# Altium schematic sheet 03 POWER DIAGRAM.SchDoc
size 420 x 297 mm
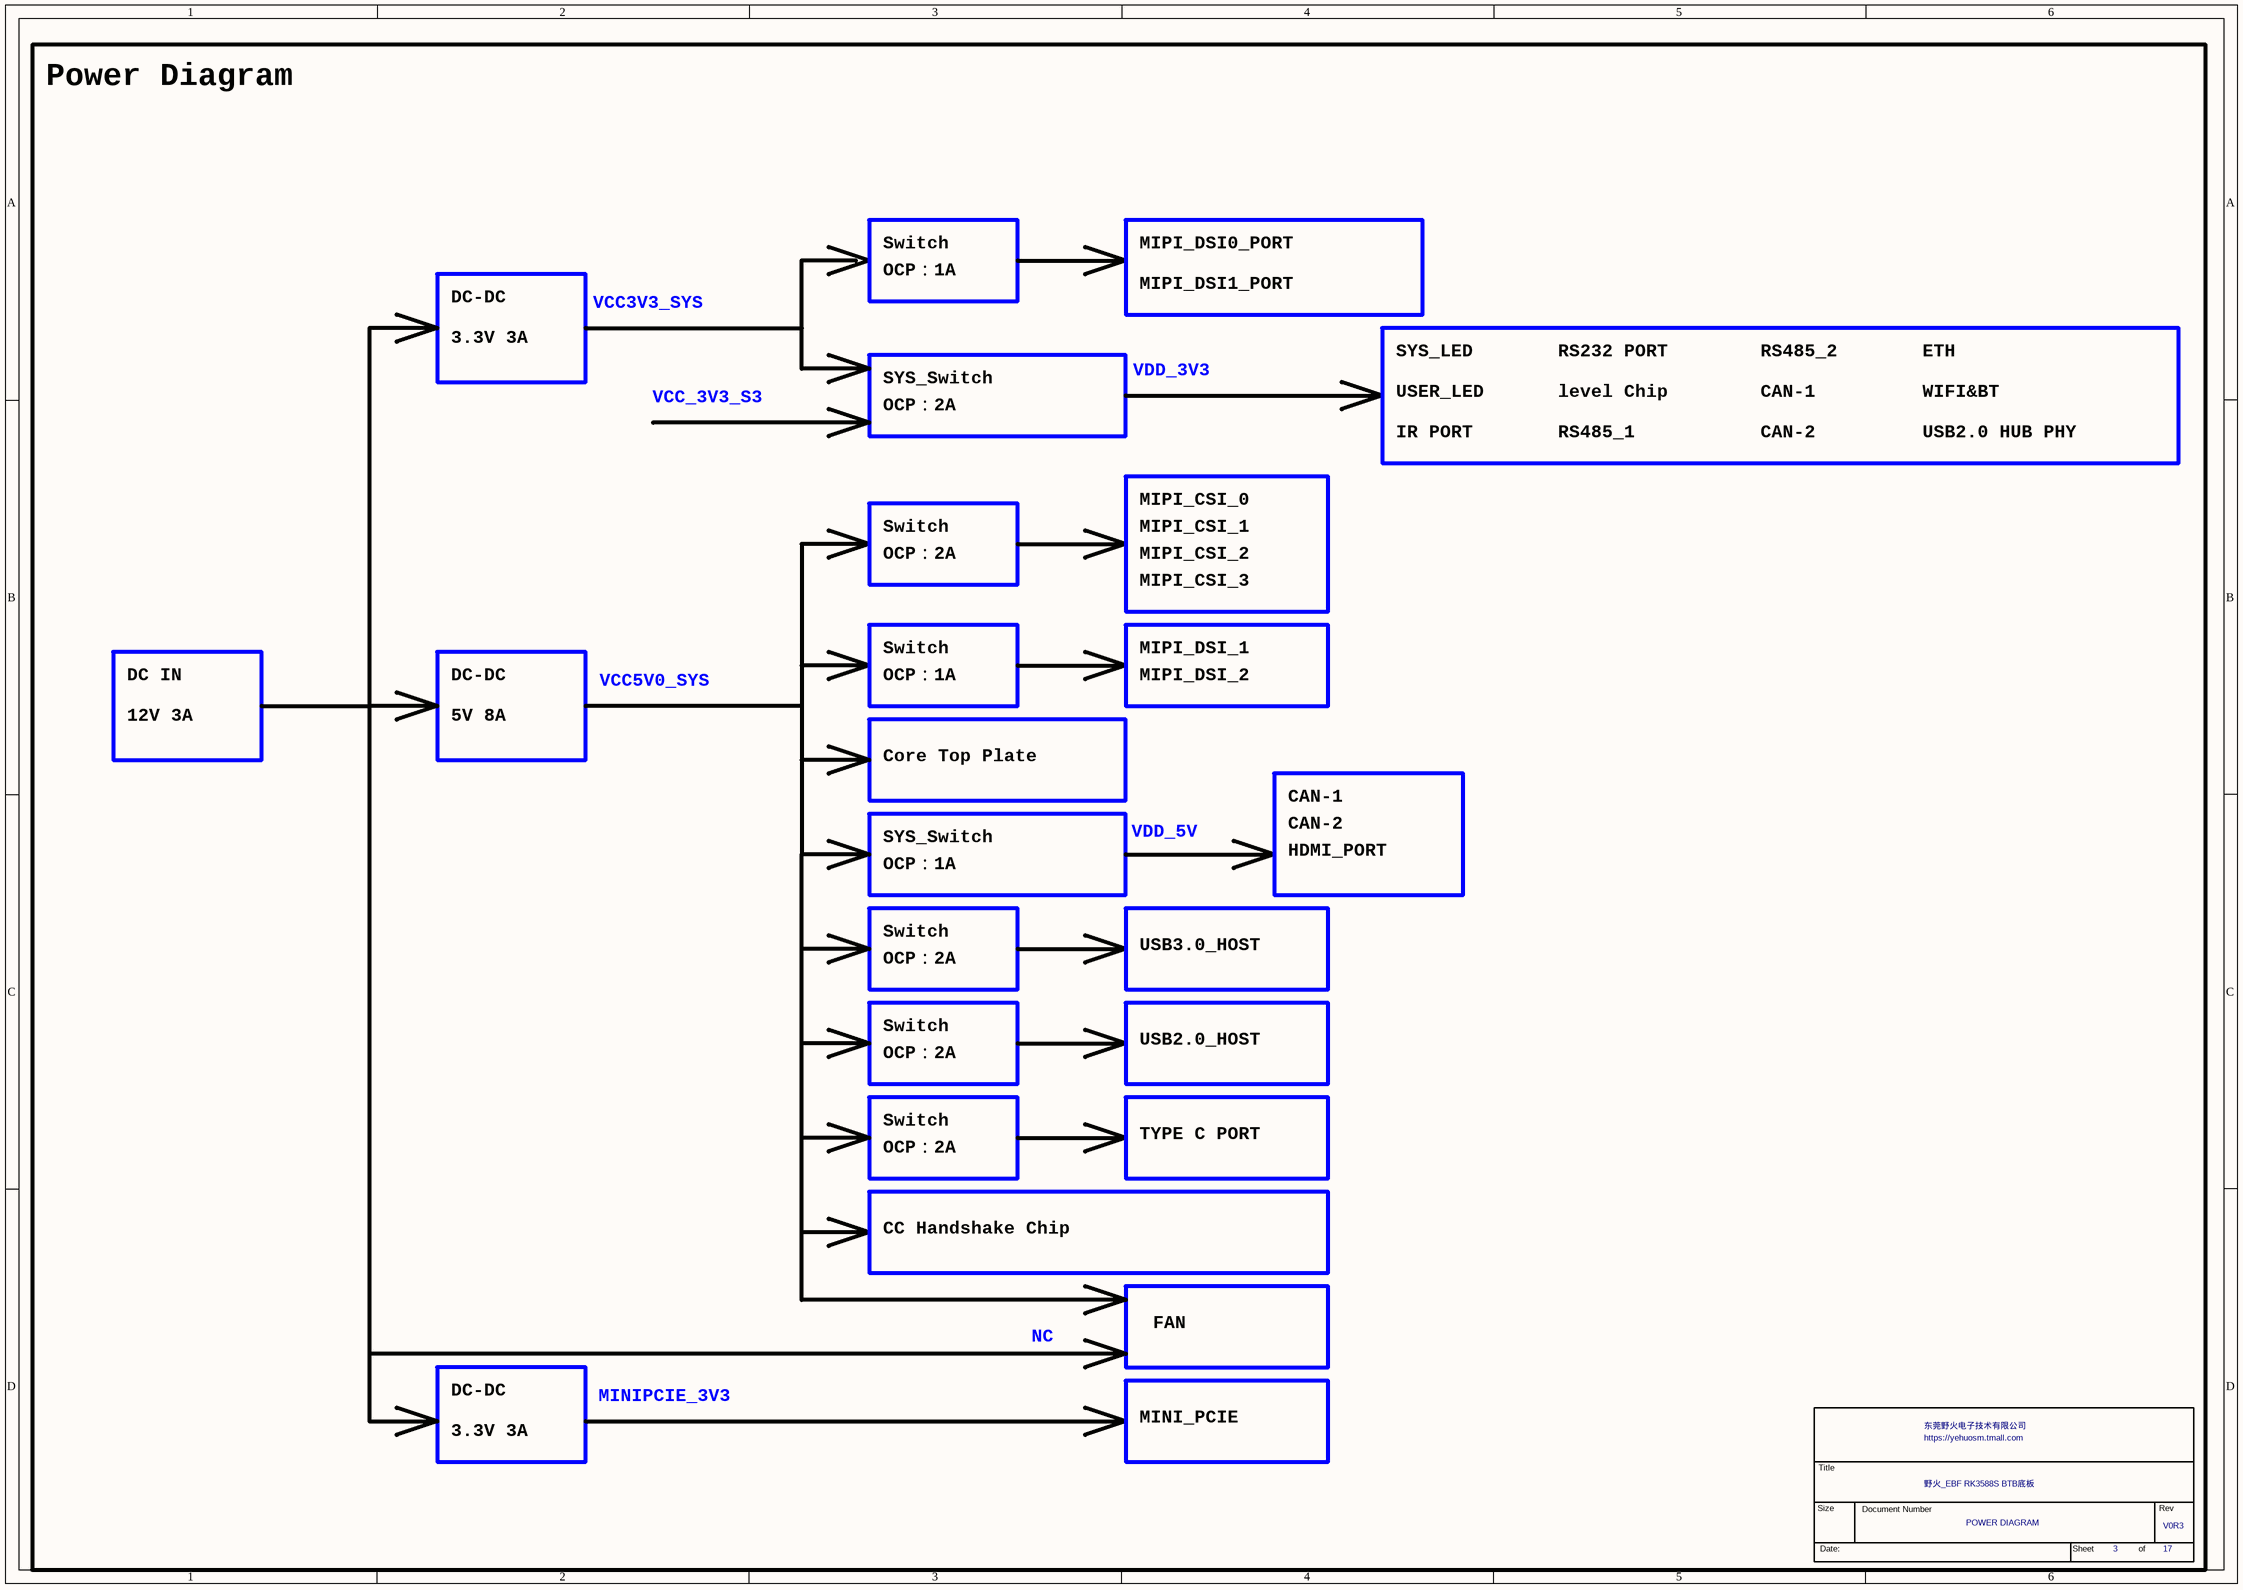
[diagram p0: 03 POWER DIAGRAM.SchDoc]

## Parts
*  Page Count: 17  Page Number: 3  OrgName: 东莞野火电子技术有限公司  Title: 野火_EBF RK3588S BTB底板  RevCode: V0R3  Doc: POWER DIAGRAM  (hidden comment: TitleBlock_YHSCH)  (graphical)

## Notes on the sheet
- Power Diagram
- Switch
- MIPI_DSI0_PORT
- DC-DC
- VCC3V3_SYS
- OCP：1A
- MIPI_DSI1_PORT
- 3.3V 3A
- SYS_Switch
- VDD_3V3
- SYS_LED
- USER_LED
- RS232 PORT
- level Chip
- RS485_2
- CAN-1
- ETH
- WIFI&BT
- VCC_3V3_S3
- OCP：2A
- IR PORT
- RS485_1
- CAN-2
- USB2.0 HUB PHY
- MIPI_CSI_0
- MIPI_CSI_1
- MIPI_CSI_2
- MIPI_CSI_3
- MIPI_DSI_1
- DC IN
- 12V 3A
- 5V 8A
- VCC5V0_SYS
- MIPI_DSI_2
- Core Top Plate
- VDD_5V
- HDMI_PORT
- USB3.0_HOST
- USB2.0_HOST
- TYPE C PORT
- CC Handshake Chip
- NC
- FAN
- MINIPCIE_3V3
- MINI_PCIE

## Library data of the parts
* = TitleBlock_YHSCH: Cage Code: 1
